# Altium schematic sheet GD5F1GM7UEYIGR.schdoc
size 127 x 101 mm
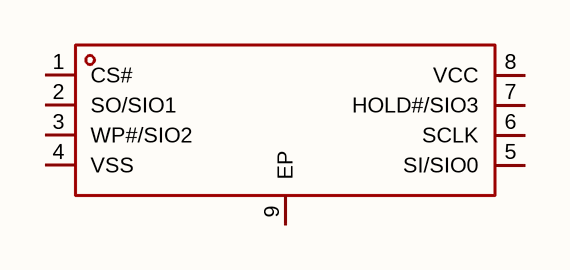
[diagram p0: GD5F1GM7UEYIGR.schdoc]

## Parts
U?  gd5f1gm7ueyigr  [WSON-8_L8.0-W6.0-P1.27-BL-EP-2]  (value not drawn)

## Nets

Not connected (* = marked no-connect by the designer): U? 1(CS#) 2(SO/SIO1) 3(WP#/SIO2) 4(VSS) 5(SI/SIO0) 6(SCLK) 7(HOLD#/SIO3) 8(VCC) 9(EP)

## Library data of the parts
U? = gd5f1gm7ueyigr: 存储容量:1Gbit;时钟频率(fc):133MHz;工作电压:2.7V~3.6V;; Manufacturer: GigaDevice(兆易创新); AddInBom: yes; Memory Size: 1Gbit; Interface: SPI; Clock Frequency: 133MHz; Page Program time (TPP): 320us; Block Erase Time(tBE): 3ms; Data Retention - TDR (Year): 10年; Standby Supply Current: 50uA; Program / Erase Cycles: 8万次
